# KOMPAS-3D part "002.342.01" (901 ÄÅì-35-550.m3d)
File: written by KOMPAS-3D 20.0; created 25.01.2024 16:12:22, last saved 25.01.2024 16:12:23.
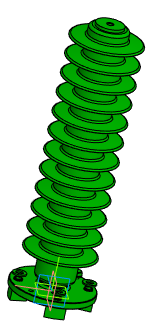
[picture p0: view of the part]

Document properties: Полное имя файла: C:\Users\drmla\OneDrive\Рабочий стол\ОПН\Модели\2 класс\ОПН-35-550.m3d

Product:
- Part/product: 002.342.01
    Масса: 0.0251123
  - Body: Тело 1
      Масса: 0.00627806
  - Body: Тело 2
      Масса: 0.00627806
  - Body: Тело 3
      Масса: 0.00627806
  - Body: Тело 4
      Масса: 0.00627806

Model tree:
1. Операция без истории:1
2. Операция без истории:2
3. Операция без истории:3
4. Операция без истории:4
5. Поверхность без истории:1
6. Поверхность без истории:2
7. Поверхность без истории:3
8. Поверхность без истории:4
9. Поверхность без истории:5
10. Поверхность без истории:6
11. Поверхность без истории:7
12. Поверхность без истории:8
13. Поверхность без истории:9
14. Поверхность без истории:10
15. Поверхность без истории:11
16. Поверхность без истории:12
17. Поверхность без истории:13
